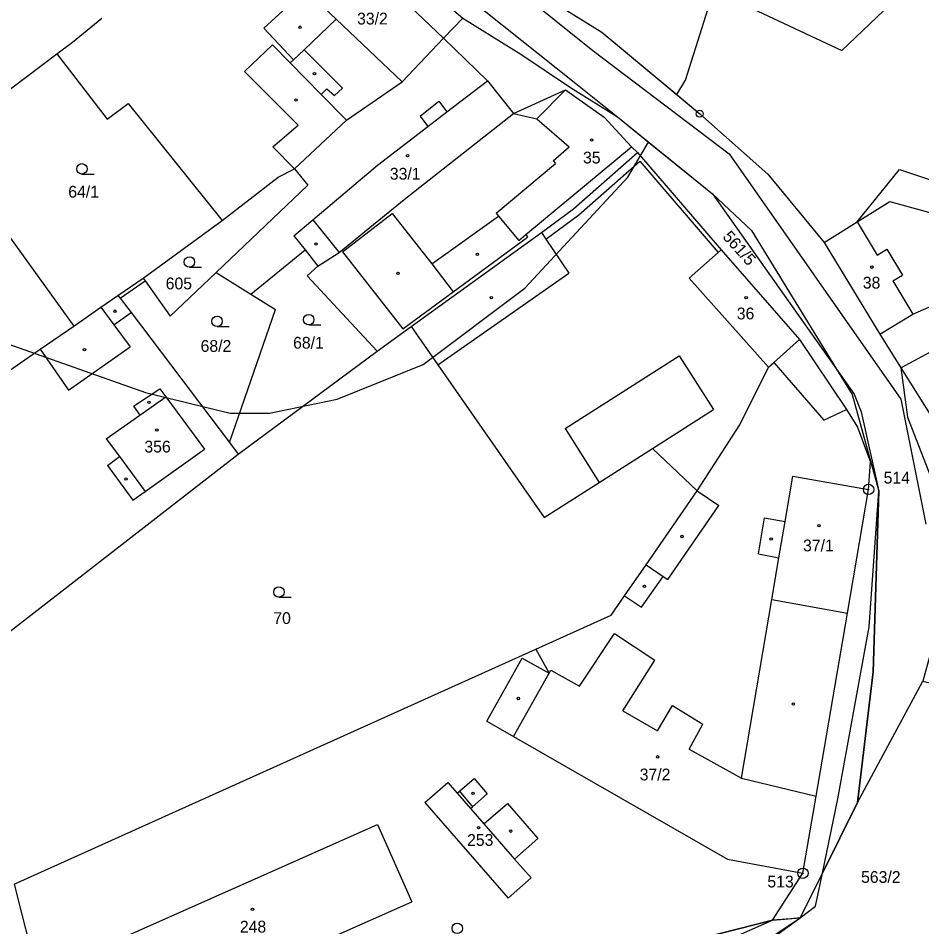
# Model space of a CAD drawing. Extents: x -725765 to -723182, y -1052705 to -1049154.
# Drawn here: x -724819.8 to -724689.6, y -1051081 to -1050950.1 of the extents above; entities that cross this region are included whole.
import ezdxf

# ---------------------------------------------------------------- set-up
doc = ezdxf.new("R2010")
doc.units = 0
for name, color, linetype in [('Vrstva 1', 7, 'Continuous'), ('Vrstva 17', 7, 'Continuous'), ('Vrstva 18', 7, 'Continuous'), ('Vrstva 19', 7, 'Continuous'), ('Vrstva 25', 7, 'Continuous'), ('Vrstva 4', 7, 'Continuous'), ('Vrstva 52', 7, 'Continuous')]:
    doc.layers.add(name, color=color, linetype=linetype)

msp = doc.modelspace()

# ---------------------------------------------------------------- linework, layer by layer
at = {"layer": 'Vrstva 1'}
for points in [[(-724769.97, -1050937.91), (-724755.76, -1050950.09)], [(-724772.04, -1050940.08), (-724758.54, -1050952.96)], [(-724749.83, -1050943.31), (-724735.73, -1050952.08)], [(-724784.45, -1050951.5), (-724778.45, -1050945.98)], [(-724701.16, -1050954.75), (-724691.11, -1050945.12)], [(-724717.03, -1050947.24), (-724701.16, -1050954.75)], [(-724812.01, -1050953.52), (-724807.78, -1050950.05)], [(-724758.54, -1050952.96), (-724755.76, -1050950.09)], [(-724755.76, -1050950.09), (-724747.39, -1050955.27)], [(-724784.45, -1050951.5), (-724780.14, -1050956.05)], [(-724735.73, -1050952.08), (-724721.63, -1050963.84)], [(-724814.26, -1050955.21), (-724812.01, -1050953.52)], [(-724764.52, -1050959.26), (-724758.54, -1050952.96)], [(-724758.54, -1050952.96), (-724752.2, -1050959.09)], [(-724831.02, -1050967.82), (-724814.26, -1050955.21)], [(-724814.26, -1050955.21), (-724807.02, -1050964.62)], [(-724747.39, -1050955.27), (-724740.23, -1050960.06)], [(-724780.63, -1050956.51), (-724780.14, -1050956.05)], [(-724780.63, -1050956.51), (-724776.17, -1050961.05)], [(-724772.52, -1050964.76), (-724764.52, -1050959.26)], [(-724752.2, -1050959.09), (-724748.45, -1050963.83)], [(-724748.45, -1050963.83), (-724740.96, -1050960.39)], [(-724740.96, -1050960.39), (-724735.37, -1050964.32)], [(-724740.23, -1050960.06), (-724733.48, -1050964.31)], [(-724776.17, -1050961.05), (-724772.52, -1050964.76)], [(-724807.02, -1050964.62), (-724804, -1050962.35)], [(-724804, -1050962.35), (-724790.46, -1050979.21)], [(-724764.21, -1050976.21), (-724748.45, -1050963.83)], [(-724735.37, -1050964.32), (-724731.46, -1050968.63)], [(-724733.48, -1050964.31), (-724719.78, -1050975.4)], [(-724721.63, -1050963.84), (-724711.83, -1050972.53)], [(-724780.04, -1050971.76), (-724772.52, -1050964.76)], [(-724831.02, -1050967.82), (-724811.84, -1050994.44)], [(-724739.79, -1050977.53), (-724730.61, -1050969.45)], [(-724731.46, -1050968.63), (-724730.61, -1050969.45)], [(-724730.61, -1050969.45), (-724718.54, -1050983.48)], [(-724782.35, -1050972.98), (-724780.04, -1050971.76)], [(-724780.04, -1050971.76), (-724778.09, -1050974.15)], [(-724790.46, -1050979.21), (-724782.35, -1050972.98)], [(-724711.83, -1050972.53), (-724703.67, -1050982.42)], [(-724791.32, -1050986.72), (-724778.09, -1050974.15)], [(-724773.57, -1050983.84), (-724764.21, -1050976.21)], [(-724719.78, -1050975.4), (-724714.16, -1050980.68)], [(-724744.43, -1050980.95), (-724739.79, -1050977.53)], [(-724698.92, -1050979.42), (-724694.22, -1050976.47)], [(-724694.22, -1050976.47), (-724682.74, -1050979.65)], [(-724801.81, -1050987.52), (-724790.46, -1050979.21)], [(-724703.67, -1050982.42), (-724698.92, -1050979.42)], [(-724763.19, -1050994.51), (-724744.43, -1050980.95)], [(-724714.16, -1050980.68), (-724701.91, -1051000.65)], [(-724703.67, -1050982.42), (-724695.66, -1050995.61)], [(-724786.31, -1050989.85), (-724778.48, -1050983.48)], [(-724778.48, -1050983.48), (-724776.64, -1050985.79)], [(-724776.64, -1050985.79), (-724773.57, -1050983.84)], [(-724718.54, -1050983.48), (-724707.22, -1050996.36)], [(-724797.92, -1050993), (-724791.32, -1050986.72)], [(-724791.32, -1050986.72), (-724786.31, -1050989.85)], [(-724778.17, -1050987.19), (-724776.64, -1050985.79)], [(-724805.46, -1050990.02), (-724801.81, -1050987.52)], [(-724801.81, -1050987.52), (-724801.52, -1050987.92)], [(-724801.52, -1050987.92), (-724797.92, -1050993)], [(-724778.17, -1050987.19), (-724768.1, -1050998.07)], [(-724690.89, -1050992.75), (-724681.69, -1050988.68)], [(-724807.91, -1050991.74), (-724805.46, -1050990.02)], [(-724805.46, -1050990.02), (-724805.16, -1050990.42)], [(-724805.16, -1050990.42), (-724803.55, -1050992.51)], [(-724786.31, -1050989.85), (-724782.78, -1050992.05)], [(-724811.84, -1050994.44), (-724807.91, -1050991.74)], [(-724803.55, -1050992.51), (-724789.39, -1051011.23)], [(-724789.39, -1051011.23), (-724782.78, -1050992.05)], [(-724695.66, -1050995.61), (-724690.89, -1050992.75)], [(-724816.65, -1050997.75), (-724811.84, -1050994.44)], [(-724768.1, -1050998.07), (-724763.19, -1050994.51)], [(-724763.19, -1050994.51), (-724759.36, -1051000.01)], [(-724695.66, -1050995.61), (-724692.63, -1051000.44)], [(-724710.96, -1050999.68), (-724707.22, -1050996.36)], [(-724707.22, -1050996.36), (-724700.48, -1051006.46)], [(-724825.71, -1051004.02), (-724816.65, -1050997.75)], [(-724788.13, -1051012.9), (-724768.1, -1050998.07)], [(-724711.72, -1051000.35), (-724710.96, -1050999.68)], [(-724759.36, -1051000.01), (-724744.02, -1051022.02)], [(-724715.86, -1051008.7), (-724711.72, -1051000.35)], [(-724701.91, -1051000.65), (-724699.66, -1051004.32)], [(-724692.63, -1051000.44), (-724687.91, -1051007.96)], [(-724803.22, -1051005.99), (-724799.43, -1051003.49)], [(-724799.43, -1051003.49), (-724798.56, -1051004.63)], [(-724798.56, -1051004.63), (-724792.97, -1051012.2)], [(-724699.66, -1051004.32), (-724695.81, -1051018.24)], [(-724803.22, -1051005.99), (-724802.31, -1051007.28)], [(-724807.14, -1051010.7), (-724802.31, -1051007.28)], [(-724700.48, -1051006.46), (-724698.87, -1051009.03)], [(-724721.98, -1051018.21), (-724715.86, -1051008.7)], [(-724698.87, -1051009.03), (-724697.01, -1051014.06)], [(-724807.14, -1051010.7), (-724805.25, -1051013.26)], [(-724789.39, -1051011.23), (-724788.13, -1051012.9)], [(-724828.56, -1051044.26), (-724788.13, -1051012.9)], [(-724801.54, -1051018.27), (-724792.97, -1051012.2)], [(-724736.1, -1051016.97), (-724728.42, -1051012.07)], [(-724728.42, -1051012.07), (-724721.98, -1051018.21)], [(-724806.97, -1051014.53), (-724805.25, -1051013.26)], [(-724697.29, -1051017.98), (-724697.01, -1051014.06)], [(-724806.97, -1051014.53), (-724803.32, -1051019.53)], [(-724744.02, -1051022.02), (-724736.1, -1051016.97)], [(-724700.34, -1051035.82), (-724697.29, -1051017.98)], [(-724803.32, -1051019.53), (-724801.54, -1051018.27)], [(-724729.36, -1051028.85), (-724721.98, -1051018.21)], [(-724696.65, -1051044.25), (-724695.81, -1051018.24)], [(-724732.44, -1051033.3), (-724729.36, -1051028.85)], [(-724734.38, -1051036.11), (-724732.44, -1051033.3)], [(-724745.23, -1051041), (-724734.38, -1051036.11)], [(-724704.85, -1051062.2), (-724700.34, -1051035.82)], [(-724738.94, -1051046.34), (-724733.89, -1051038.77)], [(-724733.89, -1051038.77), (-724728.07, -1051042.61)], [(-724820.41, -1051074.88), (-724745.23, -1051041)], [(-724745.23, -1051041), (-724743.33, -1051044.46)], [(-724752.29, -1051051.37), (-724747.22, -1051042.28)], [(-724747.22, -1051042.28), (-724743.33, -1051044.46)], [(-724732.72, -1051049.87), (-724728.07, -1051042.61)], [(-724743.33, -1051044.46), (-724743.08, -1051044.02)], [(-724743.08, -1051044.02), (-724738.94, -1051046.34)], [(-724698.87, -1051063.09), (-724696.65, -1051044.25)], [(-724698.87, -1051063.09), (-724689.48, -1051045.62)], [(-724727.7, -1051052.76), (-724725.55, -1051049.14)], [(-724725.55, -1051049.14), (-724721.16, -1051051.81)], [(-724732.72, -1051049.87), (-724727.7, -1051052.76)], [(-724752.29, -1051051.37), (-724748.44, -1051053.58)], [(-724723.16, -1051055.42), (-724721.16, -1051051.81)], [(-724748.44, -1051053.58), (-724717.62, -1051071.26)], [(-724723.16, -1051055.42), (-724715.61, -1051059.61)], [(-724756.25, -1051061.49), (-724754.14, -1051059.66)], [(-724754.14, -1051059.66), (-724752.23, -1051061.86)], [(-724715.61, -1051059.61), (-724704.85, -1051062.2)], [(-724761.23, -1051063.11), (-724757.93, -1051060.23)], [(-724757.93, -1051060.23), (-724756.58, -1051061.78)], [(-724756.58, -1051061.78), (-724756.25, -1051061.49)], [(-724754.39, -1051063.72), (-724752.23, -1051061.86)], [(-724706.75, -1051073.3), (-724704.85, -1051062.2)], [(-724761.23, -1051063.11), (-724749.23, -1051076.89)], [(-724754.67, -1051063.96), (-724754.39, -1051063.72)], [(-724754.67, -1051063.96), (-724752.72, -1051066.19)], [(-724752.72, -1051066.19), (-724749.34, -1051063.25)], [(-724749.34, -1051063.25), (-724744.93, -1051068.29)], [(-724703.95, -1051073.3), (-724698.87, -1051063.09)], [(-724809.35, -1051084.62), (-724768.06, -1051066.29)], [(-724768.06, -1051066.29), (-724763.12, -1051077.44)], [(-724748.31, -1051071.25), (-724744.93, -1051068.29)], [(-724748.31, -1051071.25), (-724745.92, -1051073.98)], [(-724717.62, -1051071.26), (-724706.75, -1051073.3)], [(-724749.23, -1051076.89), (-724745.92, -1051073.98)], [(-724711.14, -1051080.07), (-724706.75, -1051073.3)], [(-724707.16, -1051079.74), (-724703.95, -1051073.3)], [(-724820.41, -1051074.88), (-724819.35, -1051079.05)], [(-724804.38, -1051095.73), (-724763.12, -1051077.44)], [(-724819.35, -1051079.05), (-724813.42, -1051102.39)], [(-724715.11, -1051085.06), (-724707.16, -1051079.74)], [(-724711.14, -1051080.07), (-724707.16, -1051079.74)], [(-724811.24, -1051105.56), (-724711.14, -1051080.07)]]:
    msp.add_lwpolyline(points, dxfattribs=at)
at = {"layer": 'Vrstva 25'}
for points in [[(-724810.65, -1050972.53), (-724808.9, -1050972.53)], [(-724795.16, -1050985.96), (-724793.41, -1050985.96)], [(-724791.17, -1050994.51), (-724789.42, -1050994.51)], [(-724777.96, -1050994.27), (-724776.21, -1050994.27)], [(-724782.26, -1051033.52), (-724780.51, -1051033.52)]]:
    msp.add_lwpolyline(points, dxfattribs=at)
for centre, radius in [((-724779.22, -1050951.37), 0.175), ((-724777.14, -1050958.08), 0.175), ((-724779.79, -1050961.86), 0.175), ((-724721.63, -1050963.84), 0.5), ((-724721.63, -1050963.84), 0.032), ((-724737.2, -1050967.62), 0.175), ((-724763.73, -1050969.88), 0.175), ((-724810.65, -1050971.78), 0.75), ((-724776.93, -1050982.63), 0.175), ((-724753.67, -1050984.11), 0.175), ((-724795.16, -1050985.21), 0.75), ((-724765.11, -1050986.86), 0.175), ((-724696.82, -1050985.95), 0.175), ((-724751.67, -1050990.35), 0.175), ((-724714.93, -1050990.35), 0.175), ((-724805.9, -1050992.3), 0.175), ((-724791.17, -1050993.76), 0.75), ((-724777.96, -1050993.52), 0.75), ((-724810.28, -1050997.85), 0.175), ((-724800.99, -1051005.42), 0.175), ((-724799.86, -1051009.41), 0.175), ((-724804.3, -1051016.47), 0.175), ((-724697.29, -1051017.98), 0.75), ((-724697.29, -1051017.98), 0.032), ((-724704.45, -1051023.2), 0.175), ((-724724.18, -1051024.77), 0.175), ((-724711.33, -1051025.14), 0.175), ((-724782.26, -1051032.77), 0.75), ((-724729.6, -1051031.96), 0.175), ((-724747.77, -1051048.12), 0.175), ((-724708.12, -1051048.92), 0.175), ((-724727.69, -1051056.53), 0.175), ((-724754.29, -1051061.79), 0.175), ((-724753.48, -1051066.74), 0.175), ((-724748.86, -1051067.23), 0.175), ((-724706.75, -1051073.3), 0.75), ((-724706.75, -1051073.3), 0.032), ((-724786.07, -1051078.5), 0.175), ((-724756.57, -1051081.24), 0.75)]:
    msp.add_circle(centre, radius, dxfattribs=at)
at = {"layer": 'Vrstva 4'}
for points in [[(-724764.15, -1050932.92), (-724737.04, -1050954.71)], [(-724767.77, -1050936.91), (-724739.7, -1050959.28)], [(-724778.45, -1050945.98), (-724774, -1050950.22)], [(-724778.62, -1050954.61), (-724774, -1050950.22)], [(-724774, -1050950.22), (-724764.52, -1050959.26)], [(-724787.21, -1050957.75), (-724783.21, -1050953.89)], [(-724783.21, -1050953.89), (-724780.63, -1050956.51)], [(-724780.14, -1050956.05), (-724778.62, -1050954.61)], [(-724778.62, -1050954.61), (-724773.12, -1050960.16)], [(-724737.04, -1050954.71), (-724717.38, -1050969.62)], [(-724787.21, -1050957.75), (-724779.51, -1050965.47)], [(-724758.05, -1050963.57), (-724752.2, -1050959.09)], [(-724776.17, -1050961.05), (-724775.35, -1050960.24)], [(-724775.35, -1050960.24), (-724774.25, -1050961.2)], [(-724774.25, -1050961.2), (-724773.12, -1050960.16)], [(-724745.09, -1050964.58), (-724740.96, -1050960.39)], [(-724739.7, -1050959.28), (-724733.48, -1050964.31)], [(-724761.93, -1050964.17), (-724759.23, -1050962.03)], [(-724759.23, -1050962.03), (-724758.05, -1050963.57)], [(-724761.93, -1050964.17), (-724760.79, -1050965.67)], [(-724760.79, -1050965.67), (-724758.05, -1050963.57)], [(-724748.45, -1050963.83), (-724745.09, -1050964.58)], [(-724783.12, -1050968.63), (-724779.51, -1050965.47)], [(-724768.07, -1050971.25), (-724760.79, -1050965.67)], [(-724745.09, -1050964.58), (-724740.43, -1050968.63)], [(-724783.12, -1050968.63), (-724780.04, -1050971.76)], [(-724746.69, -1050981.27), (-724731.46, -1050968.63)], [(-724742.75, -1050970.65), (-724740.43, -1050968.63)], [(-724717.38, -1050969.62), (-724692.64, -1051004.98)], [(-724750.98, -1050978.18), (-724742.43, -1050971.02)], [(-724742.75, -1050970.65), (-724742.43, -1050971.02)], [(-724739.03, -1050978.39), (-724730.27, -1050970.69)], [(-724730.27, -1050970.69), (-724718.96, -1050983.85)], [(-724777.4, -1050979.15), (-724768.07, -1050971.25)], [(-724698.92, -1050979.42), (-724692.84, -1050971.9)], [(-724692.84, -1050971.9), (-724680.84, -1050975.86)], [(-724719.78, -1050975.4), (-724701.91, -1051000.65)], [(-724773.08, -1050983.76), (-724765.93, -1050978.21)], [(-724765.93, -1050978.21), (-724760.22, -1050985.49)], [(-724760.22, -1050985.49), (-724750.61, -1050978.62)], [(-724750.98, -1050978.18), (-724750.61, -1050978.62)], [(-724750.61, -1050978.62), (-724747.69, -1050982.1)], [(-724743.79, -1050981.9), (-724739.03, -1050978.39)], [(-724780.1, -1050981.44), (-724777.4, -1050979.15)], [(-724777.4, -1050979.15), (-724773.57, -1050983.84)], [(-724698.92, -1050979.42), (-724696.03, -1050984.23)], [(-724780.1, -1050981.44), (-724778.48, -1050983.48)], [(-724747.69, -1050982.1), (-724746.69, -1050981.27)], [(-724746.69, -1050981.27), (-724746.42, -1050981.63)], [(-724744.43, -1050980.95), (-724743.79, -1050981.9)], [(-724757.13, -1050989.5), (-724746.42, -1050981.63)], [(-724743.79, -1050981.9), (-724740.47, -1050986.84)], [(-724773.08, -1050983.76), (-724764.42, -1050994.86)], [(-724723.15, -1050987.54), (-724718.96, -1050983.85)], [(-724718.96, -1050983.85), (-724718.54, -1050983.48)], [(-724696.03, -1050984.23), (-724694.66, -1050983.37)], [(-724694.66, -1050983.37), (-724692.41, -1050987.12)], [(-724760.22, -1050985.49), (-724757.13, -1050989.5)], [(-724805.16, -1050990.42), (-724801.52, -1050987.92)], [(-724759.36, -1051000.01), (-724740.47, -1050986.84)], [(-724723.15, -1050987.54), (-724711.72, -1051000.35)], [(-724693.8, -1050987.93), (-724692.41, -1050987.12)], [(-724693.8, -1050987.93), (-724690.89, -1050992.75)], [(-724764.42, -1050994.86), (-724757.13, -1050989.5)], [(-724807.91, -1050991.74), (-724806.04, -1050994.26)], [(-724806.04, -1050994.26), (-724803.55, -1050992.51)], [(-724806.04, -1050994.26), (-724803.68, -1050997.43)], [(-724816.65, -1050997.75), (-724812.59, -1051003.66)], [(-724812.59, -1051003.66), (-724803.68, -1050997.43)], [(-724692.63, -1051000.44), (-724687.13, -1050997.47)], [(-724741.01, -1051009.22), (-724724.57, -1050998.72)], [(-724724.57, -1050998.72), (-724719.63, -1051006.46)], [(-724710.96, -1050999.68), (-724703.73, -1051007.99)], [(-724701.91, -1051000.65), (-724699.37, -1051004.24)], [(-724692.63, -1051000.44), (-724691.68, -1051007.59)], [(-724802.31, -1051007.28), (-724798.56, -1051004.63)], [(-724699.37, -1051004.24), (-724698.36, -1051006.8)], [(-724692.64, -1051004.98), (-724689.03, -1051022.97)], [(-724728.42, -1051012.07), (-724719.63, -1051006.46)], [(-724703.73, -1051007.99), (-724700.48, -1051006.46)], [(-724698.36, -1051006.8), (-724695.81, -1051018.24)], [(-724691.68, -1051007.59), (-724687.72, -1051017.71)], [(-724741.01, -1051009.22), (-724736.1, -1051016.97)], [(-724805.25, -1051013.26), (-724801.54, -1051018.27)], [(-724709.31, -1051022.61), (-724708.2, -1051016.08)], [(-724708.2, -1051016.08), (-724697.29, -1051017.98)], [(-724721.98, -1051018.21), (-724718.89, -1051020.31)], [(-724697.21, -1051037.81), (-724695.81, -1051018.24)], [(-724726.21, -1051030.97), (-724718.89, -1051020.31)], [(-724713.14, -1051027.29), (-724712.3, -1051022.07)], [(-724712.3, -1051022.07), (-724709.31, -1051022.61)], [(-724710.2, -1051027.83), (-724709.31, -1051022.61)], [(-724713.14, -1051027.29), (-724710.2, -1051027.83)], [(-724711.23, -1051033.87), (-724710.2, -1051027.83)], [(-724729.36, -1051028.85), (-724726.87, -1051030.52)], [(-724729.99, -1051034.93), (-724726.87, -1051030.52)], [(-724726.87, -1051030.52), (-724726.21, -1051030.97)], [(-724732.44, -1051033.3), (-724729.99, -1051034.93)], [(-724715.61, -1051059.61), (-724711.23, -1051033.87)], [(-724711.23, -1051033.87), (-724700.34, -1051035.82)], [(-724701.7, -1051062.6), (-724697.21, -1051037.81)], [(-724748.44, -1051053.58), (-724743.33, -1051044.46)], [(-724756.58, -1051061.78), (-724754.67, -1051063.96)], [(-724756.25, -1051061.49), (-724754.39, -1051063.72)], [(-724703.95, -1051073.3), (-724701.7, -1051062.6)], [(-724752.72, -1051066.19), (-724748.31, -1051071.25)], [(-724704.95, -1051078.04), (-724703.95, -1051073.3)], [(-724707.16, -1051079.74), (-724704.95, -1051078.04)], [(-724714.92, -1051085.41), (-724707.16, -1051079.74)], [(-724731.15, -1051088.89), (-724711.14, -1051080.07)]]:
    msp.add_lwpolyline(points, dxfattribs=at)
at = {"layer": 'Vrstva 52'}
for points in [[(-724813.33, -1050644), (-724808.37, -1050650.73), (-724806.43, -1050654.63), (-724804.75, -1050661.51), (-724810.21, -1050691.79), (-724815, -1050731.09), (-724815.58, -1050758.85), (-724815.13, -1050787.45), (-724817.4, -1050803.09), (-724819.59, -1050825.69), (-724818.46, -1050833.53), (-724815.27, -1050842.75), (-724807.1, -1050869.67), (-724799.84, -1050887.62), (-724790.58, -1050905.75), (-724781.27, -1050921.4), (-724774.72, -1050931.91), (-724769.97, -1050937.91), (-724755.76, -1050950.09), (-724747.39, -1050955.27), (-724740.23, -1050960.06), (-724733.48, -1050964.31), (-724729, -1050967.94)], [(-724797.81, -1050648.79), (-724786.08, -1050660.92), (-724787.52, -1050665.42), (-724789.04, -1050670.2), (-724789.99, -1050673.16), (-724795.12, -1050673.64), (-724798.75, -1050677.64), (-724800.93, -1050691.71), (-724804.92, -1050728), (-724806.68, -1050763.03), (-724806.76, -1050807.12), (-724807.68, -1050827.87), (-724807.91, -1050834.06), (-724802.7, -1050857.13), (-724793.87, -1050880.36), (-724784.64, -1050902.78), (-724767.07, -1050925.79), (-724749.83, -1050943.31), (-724735.73, -1050952.08), (-724724.93, -1050961.09)], [(-724724.93, -1050961.09), (-724723.69, -1050959), (-724719.26, -1050944.99), (-724718.63, -1050943), (-724717.88, -1050938.42), (-724717.26, -1050934.62), (-724715.44, -1050923.42), (-724715.38, -1050923), (-724712.88, -1050902.63), (-724712.19, -1050897), (-724707.69, -1050884), (-724700.69, -1050877), (-724692.38, -1050874), (-724685.73, -1050874.61), (-724681.5, -1050875), (-724671.31, -1050882), (-724668.84, -1050884.53), (-724650.81, -1050903), (-724630.31, -1050928), (-724612.38, -1050961), (-724597.47, -1050993.67)], [(-724724.93, -1050961.09), (-724721.63, -1050963.84), (-724711.83, -1050972.53), (-724703.67, -1050982.42), (-724695.66, -1050995.61), (-724692.63, -1051000.44), (-724687.91, -1051007.96), (-724687.72, -1051017.71), (-724687.95, -1051027.39), (-724688.2, -1051037.96), (-724688.28, -1051041.27), (-724689.48, -1051045.62), (-724687.9, -1051046.02)], [(-724821.31, -1050997), (-724801.5, -1051004), (-724789.31, -1051007), (-724783.63, -1051007), (-724773.88, -1051005), (-724761.5, -1051000), (-724746.81, -1050989), (-724732, -1050973), (-724730.19, -1050969.94), (-724729, -1050967.94)], [(-724729, -1050967.94), (-724719.78, -1050975.4), (-724714.16, -1050980.68), (-724701.91, -1051000.65), (-724699.66, -1051004.32), (-724695.81, -1051018.24), (-724696.65, -1051044.25), (-724698.87, -1051063.09), (-724703.95, -1051073.3), (-724705.71, -1051076.84), (-724707.16, -1051079.74), (-724708.49, -1051079.85), (-724711.14, -1051080.07), (-724811.24, -1051105.56)]]:
    msp.add_lwpolyline(points, dxfattribs=at)

# ---------------------------------------------------------------- texts
at = {"layer": 'Vrstva 17'}
for s, p in [('514', (-724695.12, -1051017.14)), ('513', (-724711.87, -1051075.35))]:
    msp.add_text(s, height=1.7, dxfattribs=at).set_placement(p)
at = {"layer": 'Vrstva 18'}
for s, p in [('64/1', (-724812.62, -1050975.93)), ('605', (-724798.58, -1050989.15)), ('68/1', (-724780.22, -1050997.7)), ('68/2', (-724793.55, -1050998.16)), ('70', (-724783.07, -1051037.38)), ('563/2', (-724698.37, -1051074.69))]:
    msp.add_text(s, height=1.7, dxfattribs=at).set_placement(p)
msp.add_text('561/5', height=1.7, rotation=311.9025, dxfattribs=at).set_placement((-724718.43, -1050981.65))
at = {"layer": 'Vrstva 19'}
for s, p in [('33/2', (-724771, -1050950.98)), ('35', (-724738.44, -1050971.01)), ('33/1', (-724766.28, -1050973.34)), ('38', (-724698.12, -1050989.04)), ('36', (-724716.28, -1050993.48)), ('356', (-724801.65, -1051012.67)), ('37/1', (-724706.73, -1051026.91)), ('37/2', (-724730.27, -1051059.92)), ('253', (-724755.15, -1051069.35)), ('248', (-724787.89, -1051081.85))]:
    msp.add_text(s, height=1.7, dxfattribs=at).set_placement(p)

doc.saveas('drawing.dxf')
